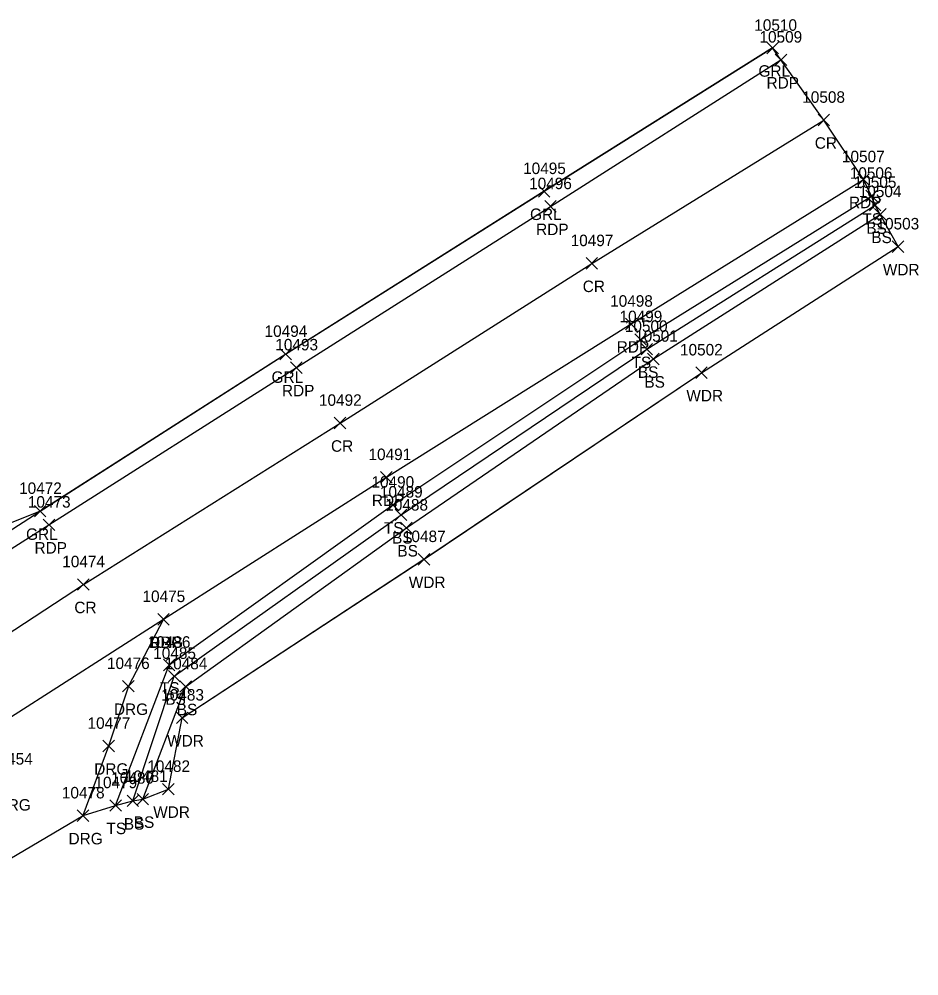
# Model space of a CAD drawing. Extents: x 1651685 to 1653558, y 889533 to 891085.
# Drawn here: x 1653187.7 to 1653344.3, y 890787.2 to 890953.8 of the extents above; entities that cross this region are included whole.
import ezdxf

# ---------------------------------------------------------------- set-up
doc = ezdxf.new("R2010")
doc.units = 0
for name, color, linetype in [('L_A', 7, 'Continuous'), ('L_I', 7, 'Continuous'), ('L_TIC', 7, 'Continuous'), ('LAWA', 7, 'Continuous'), ('LELB', 7, 'Continuous'), ('LSOGP', 7, 'Continuous'), ('P_A', 7, 'Continuous'), ('P_I', 7, 'Continuous'), ('P_TIC', 7, 'Continuous'), ('PET', 7, 'Continuous'), ('PRC', 7, 'Continuous'), ('R_A', 7, 'Continuous'), ('R_I', 7, 'Continuous'), ('R_TIC', 7, 'Continuous'), ('RDG', 7, 'Continuous'), ('RGR', 7, 'Continuous')]:
    doc.layers.add(name, color=color, linetype=linetype)

msp = doc.modelspace()

# ---------------------------------------------------------------- linework, layer by layer
at = {"layer": 'L_TIC'}
for points in [[(1653335.06, 890921.97), (1653337.06, 890923.97)], [(1653337.06, 890921.97), (1653335.06, 890923.97)], [(1653335.69, 890920.39), (1653337.69, 890922.39)], [(1653337.69, 890920.39), (1653335.69, 890922.39)], [(1653336.57, 890918.77), (1653338.57, 890920.77)], [(1653338.57, 890918.77), (1653336.57, 890920.77)], [(1653339.66, 890913.15), (1653341.66, 890915.15)], [(1653341.66, 890913.15), (1653339.66, 890915.15)], [(1653294.87, 890897), (1653296.87, 890899)], [(1653296.87, 890897), (1653294.87, 890899)], [(1653295.94, 890895.31), (1653297.94, 890897.31)], [(1653297.94, 890895.31), (1653295.94, 890897.31)], [(1653297.08, 890893.6), (1653299.08, 890895.6)], [(1653299.08, 890893.6), (1653297.08, 890895.6)], [(1653305.46, 890891.21), (1653307.46, 890893.21)], [(1653307.46, 890891.21), (1653305.46, 890893.21)], [(1653251.75, 890868.18), (1653253.75, 890870.18)], [(1653253.75, 890868.18), (1653251.75, 890870.18)], [(1653253.16, 890866.46), (1653255.16, 890868.46)], [(1653255.16, 890866.46), (1653253.16, 890868.46)], [(1653254.08, 890864.2), (1653256.08, 890866.2)], [(1653256.08, 890864.2), (1653254.08, 890866.2)], [(1653257.15, 890858.71), (1653259.15, 890860.71)], [(1653259.15, 890858.71), (1653257.15, 890860.71)], [(1653212.78, 890840.32), (1653214.78, 890842.32)], [(1653214.78, 890840.32), (1653212.78, 890842.32)], [(1653213.69, 890838.38), (1653215.69, 890840.38)], [(1653215.69, 890838.38), (1653213.69, 890840.38)], [(1653215.68, 890836.56), (1653217.68, 890838.56)], [(1653217.68, 890836.56), (1653215.68, 890838.56)], [(1653215.07, 890831.12), (1653217.07, 890833.12)], [(1653217.07, 890831.12), (1653215.07, 890833.12)], [(1653212.66, 890818.7), (1653214.66, 890820.7)], [(1653214.66, 890818.7), (1653212.66, 890820.7)], [(1653208.2, 890816.95), (1653210.2, 890818.95)], [(1653210.2, 890816.95), (1653208.2, 890818.95)], [(1653203.47, 890815.86), (1653205.47, 890817.86)], [(1653205.47, 890815.86), (1653203.47, 890817.86)], [(1653206.47, 890816.65), (1653208.47, 890818.65)], [(1653208.47, 890816.65), (1653206.47, 890818.65)]]:
    msp.add_lwpolyline(points, dxfattribs=at)
at = {"layer": 'LAWA'}
msp.add_lwpolyline([(1653213.66, 890819.7), (1653216.07, 890832.12), (1653258.15, 890859.71), (1653306.46, 890892.21), (1653340.66, 890914.15)], dxfattribs=at)
at = {"layer": 'LELB'}
for points in [[(1653204.47, 890816.86), (1653213.78, 890841.32), (1653252.75, 890869.18), (1653295.87, 890898), (1653336.06, 890922.97)], [(1653207.47, 890817.65), (1653214.69, 890839.38), (1653254.16, 890867.46), (1653296.94, 890896.31), (1653336.69, 890921.39)], [(1653209.2, 890817.95), (1653216.68, 890837.56), (1653255.08, 890865.2), (1653298.08, 890894.6), (1653337.57, 890919.77)]]:
    msp.add_lwpolyline(points, dxfattribs=at)
at = {"layer": 'LSOGP'}
msp.add_lwpolyline([(1653182.19, 890805.28), (1653198.8, 890815.08), (1653204.47, 890816.86), (1653207.47, 890817.65), (1653209.2, 890817.95), (1653213.65, 890819.7), (1653216.07, 890832.12), (1653258.16, 890859.71), (1653306.46, 890892.21), (1653340.67, 890914.15), (1653337.57, 890919.76), (1653336.69, 890921.39), (1653336.06, 890922.97), (1653334.64, 890925.85), (1653327.74, 890936.2), (1653320.29, 890946.68), (1653318.83, 890948.74), (1653279.07, 890923.79), (1653234.08, 890895.44), (1653191.35, 890868.11), (1653139.25, 890847.21)], dxfattribs=at)
at = {"layer": 'P_TIC'}
for points in [[(1653319.29, 890945.68), (1653321.29, 890947.68)], [(1653321.29, 890945.68), (1653319.29, 890947.68)], [(1653326.74, 890935.2), (1653328.74, 890937.2)], [(1653328.74, 890935.2), (1653326.74, 890937.2)], [(1653333.65, 890924.85), (1653335.65, 890926.85)], [(1653335.65, 890924.85), (1653333.65, 890926.85)], [(1653279.18, 890920.16), (1653281.18, 890922.16)], [(1653281.18, 890920.16), (1653279.18, 890922.16)], [(1653286.35, 890910.24), (1653288.35, 890912.24)], [(1653288.35, 890910.24), (1653286.35, 890912.24)], [(1653293.22, 890899.69), (1653295.22, 890901.69)], [(1653295.22, 890899.69), (1653293.22, 890901.69)], [(1653234.94, 890892.09), (1653236.94, 890894.09)], [(1653236.94, 890892.09), (1653234.94, 890894.09)], [(1653242.54, 890882.44), (1653244.54, 890884.44)], [(1653244.54, 890882.44), (1653242.54, 890884.44)], [(1653250.6, 890872.99), (1653252.6, 890874.99)], [(1653252.6, 890872.99), (1653250.6, 890874.99)], [(1653191.87, 890864.71), (1653193.87, 890866.71)], [(1653193.87, 890864.71), (1653191.87, 890866.71)], [(1653197.86, 890854.33), (1653199.86, 890856.33)], [(1653199.86, 890854.33), (1653197.86, 890856.33)], [(1653211.82, 890848.27), (1653213.82, 890850.27)], [(1653213.82, 890848.27), (1653211.82, 890850.27)]]:
    msp.add_lwpolyline(points, dxfattribs=at)
at = {"layer": 'PET'}
for points in [[(1652776.68, 890458.63), (1652791.9, 890507.53), (1652801.72, 890533.82), (1652810.09, 890553.36), (1652823.07, 890577.38), (1652836.65, 890598.71), (1652853.5, 890620.62), (1652874.5, 890644.55), (1652894.69, 890663.43), (1652909.83, 890677.02), (1652929.28, 890691.96), (1652967.44, 890717.98), (1652993.7, 890736.14), (1653032.31, 890761.89), (1653070.4, 890786.93), (1653112.15, 890813.99), (1653148.48, 890837.47), (1653192.87, 890865.71), (1653235.94, 890893.09), (1653280.18, 890921.16), (1653320.29, 890946.68)], [(1652797.7, 890444.76), (1652815.98, 890499.36), (1652826.44, 890526.94), (1652833.17, 890541.97), (1652844.38, 890563.93), (1652857.27, 890583.87), (1652872.84, 890604.95), (1652891.59, 890626.08), (1652910.84, 890643.86), (1652926.01, 890657.3), (1652944.49, 890672.05), (1652975.79, 890694.46), (1653007.52, 890715.91), (1653044.82, 890740.95), (1653083.79, 890766.34), (1653126.92, 890794.39), (1653162.42, 890817.19), (1653177.23, 890826.53), (1653212.82, 890849.27), (1653251.6, 890873.99), (1653294.22, 890900.69), (1653334.65, 890925.85)]]:
    msp.add_lwpolyline(points, dxfattribs=at)
at = {"layer": 'PRC'}
msp.add_lwpolyline([(1652786.21, 890448.94), (1652804.54, 890503.78), (1652815.08, 890532.72), (1652822.08, 890547.99), (1652834.04, 890571.05), (1652846.73, 890591.11), (1652862.72, 890612.73), (1652882.99, 890635.62), (1652902.76, 890654.37), (1652917.73, 890667.19), (1652936.47, 890681.71), (1652967.99, 890703.84), (1653000.43, 890726.04), (1653038.85, 890751.54), (1653077.14, 890776.73), (1653119.4, 890804.03), (1653156.21, 890827.39), (1653198.86, 890855.33), (1653243.54, 890883.44), (1653287.35, 890911.24), (1653327.74, 890936.2)], dxfattribs=at)
at = {"layer": 'R_TIC'}
for points in [[(1653317.83, 890947.74), (1653319.83, 890949.74)], [(1653319.83, 890947.74), (1653317.83, 890949.74)], [(1653278.07, 890922.79), (1653280.07, 890924.79)], [(1653280.07, 890922.79), (1653278.07, 890924.79)], [(1653233.07, 890894.44), (1653235.07, 890896.44)], [(1653235.07, 890894.44), (1653233.07, 890896.44)], [(1653190.34, 890867.1), (1653192.34, 890869.1)], [(1653192.34, 890867.1), (1653190.34, 890869.1)], [(1653211.82, 890848.27), (1653213.82, 890850.27)], [(1653213.82, 890848.27), (1653211.82, 890850.27)], [(1653205.69, 890836.61), (1653207.69, 890838.61)], [(1653207.69, 890836.61), (1653205.69, 890838.61)], [(1653202.26, 890826.2), (1653204.26, 890828.2)], [(1653204.26, 890826.2), (1653202.26, 890828.2)], [(1653197.79, 890814.08), (1653199.79, 890816.08)], [(1653199.79, 890814.08), (1653197.79, 890816.08)]]:
    msp.add_lwpolyline(points, dxfattribs=at)
at = {"layer": 'RDG'}
msp.add_lwpolyline([(1653212.82, 890849.27), (1653206.69, 890837.61), (1653203.26, 890827.2), (1653198.79, 890815.08)], dxfattribs=at)
at = {"layer": 'RGR'}
msp.add_lwpolyline([(1652753.62, 890407.5), (1652763.75, 890431.04), (1652774.48, 890459.79), (1652790.93, 890508.17), (1652800.51, 890534.29), (1652809.1, 890554.07), (1652821.88, 890578.18), (1652835.53, 890599.08), (1652852.44, 890621.25), (1652873.86, 890645.38), (1652894.3, 890664.88), (1652909.53, 890677.55), (1652928.71, 890692.69), (1652967.13, 890720.62), (1652991.99, 890738.03), (1653030.5, 890764.27), (1653069.01, 890789.08), (1653110.73, 890816.31), (1653147.12, 890839.54), (1653191.34, 890868.1), (1653234.07, 890895.44), (1653279.07, 890923.79), (1653318.83, 890948.74)], dxfattribs=at)

# ---------------------------------------------------------------- texts
at = {"layer": 'L_A'}
for s, p in [('TS', (1653334.47, 890917.97)), ('BS', (1653335.13, 890916.39)), ('BS', (1653336.01, 890914.77)), ('WDR', (1653338.02, 890909.15)), ('TS', (1653294.28, 890893)), ('BS', (1653295.38, 890891.31)), ('BS', (1653296.52, 890889.6)), ('WDR', (1653303.82, 890887.21)), ('TS', (1653251.16, 890864.18)), ('BS', (1653252.6, 890862.46)), ('BS', (1653253.52, 890860.2)), ('WDR', (1653255.51, 890854.71)), ('TS', (1653212.19, 890836.32)), ('BS', (1653213.13, 890834.38)), ('BS', (1653215.12, 890832.56)), ('WDR', (1653213.44, 890827.12)), ('WDR', (1653211.02, 890814.7)), ('TS', (1653202.88, 890811.86)), ('BS', (1653205.91, 890812.65)), ('BS', (1653207.64, 890812.95))]:
    msp.add_text(s, height=2, dxfattribs=at).set_placement(p)
at = {"layer": 'L_I'}
for s, p in [('10506', (1653332.26, 890925.97)), ('10505', (1653332.94, 890924.39)), ('10504', (1653333.82, 890922.77)), ('10503', (1653336.91, 890917.15)), ('10499', (1653292.19, 890901)), ('10500', (1653293.11, 890899.31)), ('10501', (1653294.9, 890897.6)), ('10502', (1653302.71, 890895.21)), ('10490', (1653249, 890872.18)), ('10489', (1653250.48, 890870.46)), ('10488', (1653251.41, 890868.2)), ('10487', (1653254.48, 890862.71)), ('10486', (1653210.06, 890844.32)), ('10485', (1653211.02, 890842.38)), ('10484', (1653213.01, 890840.56)), ('10483', (1653212.41, 890835.12)), ('10482', (1653209.99, 890822.7)), ('10480', (1653203.71, 890820.65)), ('10481', (1653206.1, 890820.95)), ('10479', (1653200.79, 890819.86))]:
    msp.add_text(s, height=2, dxfattribs=at).set_placement(p)
at = {"layer": 'P_A'}
for s, p in [('RDP', (1653317.78, 890941.68)), ('CR', (1653326.17, 890931.2)), ('RDP', (1653332.13, 890920.85)), ('RDP', (1653277.67, 890916.16)), ('CR', (1653285.78, 890906.24)), ('RDP', (1653291.7, 890895.69)), ('RDP', (1653233.43, 890888.09)), ('CR', (1653241.97, 890878.44)), ('RDP', (1653249.08, 890868.99)), ('RDP', (1653190.36, 890860.71)), ('CR', (1653197.29, 890850.33)), ('RDP', (1653210.31, 890844.27))]:
    msp.add_text(s, height=2, dxfattribs=at).set_placement(p)
at = {"layer": 'P_I'}
for s, p in [('10509', (1653316.54, 890949.68)), ('10508', (1653323.99, 890939.2)), ('10507', (1653330.9, 890928.85)), ('10496', (1653276.45, 890924.16)), ('10497', (1653283.68, 890914.24)), ('10498', (1653290.55, 890903.69)), ('10493', (1653232.27, 890896.09)), ('10492', (1653239.87, 890886.44)), ('10491', (1653248.49, 890876.99)), ('10473', (1653189.2, 890868.71)), ('10474', (1653195.19, 890858.33)), ('10475', (1653209.15, 890852.27))]:
    msp.add_text(s, height=2, dxfattribs=at).set_placement(p)
at = {"layer": 'R_A'}
for s, p in [('GRL', (1653316.37, 890943.74)), ('GRL', (1653276.61, 890918.79)), ('GRL', (1653231.62, 890890.44)), ('GRL', (1653188.89, 890863.1)), ('DRG', (1653210.31, 890844.27)), ('DRG', (1653204.18, 890832.61)), ('DRG', (1653200.75, 890822.2)), ('DRG', (1653183.76, 890815.96)), ('DRG', (1653196.28, 890810.08))]:
    msp.add_text(s, height=2, dxfattribs=at).set_placement(p)
at = {"layer": 'R_I'}
for s, p in [('10510', (1653315.64, 890951.74)), ('10495', (1653275.4, 890926.79)), ('10494', (1653230.4, 890898.44)), ('10472', (1653187.67, 890871.1)), ('10475', (1653209.15, 890852.27)), ('10476', (1653202.97, 890840.61)), ('10477', (1653199.59, 890830.2)), ('10454', (1653182.61, 890823.96)), ('10478', (1653195.12, 890818.08))]:
    msp.add_text(s, height=2, dxfattribs=at).set_placement(p)

doc.saveas('drawing.dxf')
